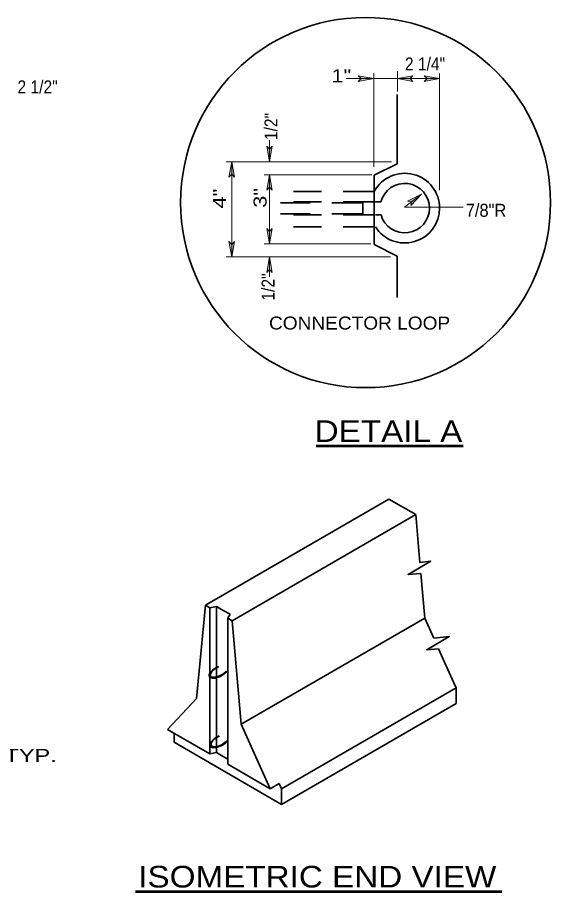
# Model space of a CAD drawing. Extents: x 12.4 to 19.4, y 5.8 to 15.9.
# Drawn here: x 16.975 to 19.442, y 11.795 to 15.837 of the extents above; entities that cross this region are included whole.
import ezdxf
from ezdxf.enums import TextEntityAlignment as Align

# ---------------------------------------------------------------- set-up
doc = ezdxf.new("R2010")
doc.units = 0
doc.header["$LTSCALE"] = 0.024
doc.linetypes.add('LONG_DASHED', pattern=[7.5, 6, -1.5])
for name, color, linetype, lineweight in [('1', 7, 'Continuous', 35), ('10', 7, 'Continuous', 13), ('12', 7, 'Continuous', 53)]:
    doc.layers.add(name, color=color, linetype=linetype, lineweight=lineweight)

msp = doc.modelspace()

# ---------------------------------------------------------------- hatches: boundary and pattern name
at = {"layer": '10'}
for points in [[(18.5521, 15.5671), (18.6236, 15.5545), (18.5521, 15.5419), (18.5656, 15.5545)], [(18.8053, 15.542), (18.7338, 15.5546), (18.8053, 15.5672), (18.7918, 15.5546)], [(18.8573, 15.5672), (18.9288, 15.5546), (18.8573, 15.542), (18.8708, 15.5546)], [(18.1544, 15.2418), (18.1418, 15.1703), (18.1292, 15.2418), (18.1418, 15.2283)], [(17.9538, 15.0988), (17.9664, 15.1703), (17.979, 15.0988), (17.9664, 15.1123)], [(18.1292, 15.0388), (18.1418, 15.1103), (18.1544, 15.0388), (18.1418, 15.0523)], [(18.7808, 14.9881), (18.8456, 15.0208), (18.7959, 14.9679), (18.7992, 14.9861)], [(18.1544, 14.8614), (18.1418, 14.7899), (18.1292, 14.8614), (18.1418, 14.8479)], [(17.979, 14.8014), (17.9664, 14.7299), (17.9538, 14.8014), (17.9664, 14.7879)], [(18.1292, 14.6584), (18.1418, 14.7299), (18.1544, 14.6584), (18.1418, 14.6719)]]:
    msp.add_hatch(color=256, dxfattribs=at).paths.add_polyline_path(points)

# ---------------------------------------------------------------- linework, layer by layer
at = {"layer": '1'}
for p, q in [((18.7329, 15.161), (18.7329, 15.4814)), ((18.6261, 15.1076), (18.7329, 15.161)), ((18.6261, 14.7874), (18.6261, 15.1076)), ((18.6261, 14.9846), (18.657, 14.9846)), ((18.6315, 14.9245), (18.6575, 14.9245)), ((18.6261, 14.7874), (18.7329, 14.7341)), ((18.7329, 14.5422), (18.7329, 14.7341)), ((17.8447, 13.1191), (18.6943, 13.6096)), ((18.8187, 13.5379), (18.6943, 13.6096)), ((17.969, 13.0473), (18.8187, 13.5379)), ((18.8187, 13.5379), (18.8377, 13.3173)), ((18.8601, 13.0593), (18.8422, 13.2662)), ((17.8032, 12.6883), (17.8447, 13.1191)), ((17.8654, 13.1071), (17.8447, 13.1191)), ((17.8964, 13.1131), (17.8654, 13.1071)), ((17.8654, 13.1071), (17.8654, 12.8057)), ((17.9275, 13.0951), (17.8964, 13.1131)), ((17.8964, 13.1131), (17.8964, 12.832)), ((17.9587, 13.0772), (17.9275, 13.0951)), ((17.9587, 13.0772), (17.9483, 13.0593)), ((17.9483, 13.0593), (17.969, 13.0473)), ((17.9483, 13.0593), (17.9483, 12.3832)), ((18.0105, 12.5686), (18.8601, 13.0593)), ((18.8601, 13.0593), (18.9019, 12.9662)), ((17.969, 13.0473), (18.0105, 12.5686)), ((18.9943, 12.7603), (18.9239, 12.9173)), ((17.8964, 12.4371), (17.8964, 12.832)), ((17.8654, 12.4311), (17.8654, 12.7849)), ((17.8997, 12.7822), (17.8998, 12.7822)), ((18.197, 12.2695), (19.0052, 12.7362)), ((18.9943, 12.7603), (19.0052, 12.7362)), ((19.0052, 12.6644), (19.0052, 12.7362)), ((17.8032, 12.6883), (17.669, 12.5444)), ((18.197, 12.1978), (19.0052, 12.6643)), ((17.669, 12.5444), (17.8654, 12.4311)), ((18.0105, 12.5686), (18.1447, 12.2698)), ((17.6995, 12.4849), (17.6995, 12.5261)), ((18.197, 12.1978), (17.6996, 12.485)), ((17.8964, 12.4371), (17.8654, 12.4311)), ((17.9275, 12.4192), (17.8964, 12.4371)), ((17.9483, 12.4072), (17.9275, 12.4192)), ((18.1447, 12.2698), (17.9483, 12.3832)), ((18.1861, 12.2938), (18.1447, 12.2698)), ((18.1861, 12.2938), (18.197, 12.2695)), ((18.197, 12.1978), (18.197, 12.2695))]:
    msp.add_line(p, q, dxfattribs=at)
at = {"layer": '1', "linetype": 'LONG_DASHED'}
for p, q in [((18.6261, 15.0331), (18.2521, 15.0331)), ((18.5732, 14.9802), (18.1919, 14.9802)), ((18.6261, 14.9846), (18.2521, 14.9846)), ((18.5732, 14.9802), (18.5732, 14.9292)), ((18.5732, 14.9292), (18.1919, 14.9292)), ((18.6261, 14.9245), (18.2521, 14.9245)), ((18.6261, 14.8691), (18.2521, 14.8691))]:
    msp.add_line(p, q, dxfattribs=at)
at = {"layer": '1'}
msp.add_circle((18.58605, 14.98141), 0.85609, dxfattribs=at)
for centre, major_axis in [((17.90761, 12.81221), (-0.04433, -0.02381)), ((17.90814, 12.81332), (-0.03989, -0.02143)), ((17.91106, 12.49087), (-0.04433, -0.02381)), ((17.91159, 12.49199), (-0.03989, -0.02143))]:
    msp.add_ellipse(centre, major_axis=major_axis, ratio=0.443253, start_param=4.5260757, end_param=8.573904, dxfattribs=at)
at = {"layer": '10'}
for p, q in [((18.6236, 15.5545), (18.5521, 15.5671)), ((18.6236, 15.1472), (18.6236, 15.5795)), ((18.7332, 15.4956), (18.7332, 15.5897)), ((18.7338, 15.5546), (18.8053, 15.5672)), ((18.9288, 15.5546), (18.8573, 15.5672)), ((18.9288, 15.0381), (18.9288, 15.579)), ((18.4964, 15.5546), (18.9288, 15.5546)), ((18.6236, 15.5545), (18.5521, 15.5419)), ((18.7338, 15.5546), (18.8053, 15.542)), ((18.9288, 15.5546), (18.8573, 15.542)), ((18.1418, 15.1703), (18.1292, 15.2418)), ((18.1418, 15.1703), (18.1418, 15.2706)), ((18.1418, 15.1703), (18.1544, 15.2418)), ((18.7061, 15.1703), (17.9414, 15.1703)), ((17.9664, 15.1703), (17.9538, 15.0988)), ((17.9664, 15.1703), (17.979, 15.0988)), ((17.9664, 15.1703), (17.9664, 14.7299)), ((18.6144, 15.1103), (18.1168, 15.1103)), ((18.1418, 15.1103), (18.1292, 15.0388)), ((18.1418, 15.1103), (18.1544, 15.0388)), ((18.1418, 15.1103), (18.1418, 14.7899)), ((18.8456, 15.0208), (18.7655, 14.9609)), ((18.8456, 15.0208), (18.7808, 14.9881)), ((18.8456, 15.0208), (18.7959, 14.9679)), ((19.0385, 14.9609), (18.7655, 14.9609)), ((18.1418, 14.7899), (18.1292, 14.8614)), ((18.1418, 14.7899), (18.1544, 14.8614)), ((17.9664, 14.7299), (17.9538, 14.8014)), ((17.9664, 14.7299), (17.979, 14.8014)), ((18.61, 14.7899), (18.1168, 14.7899)), ((18.7017, 14.7299), (17.9414, 14.7299)), ((18.1418, 14.7299), (18.1292, 14.6584)), ((18.1418, 14.7299), (18.1418, 14.6373)), ((18.1418, 14.7299), (18.1544, 14.6584))]:
    msp.add_line(p, q, dxfattribs=at)
for points in [[(18.5521, 15.5671), (18.5656, 15.5545), (18.5521, 15.5419)], [(18.8053, 15.542), (18.7918, 15.5546), (18.8053, 15.5672)], [(18.8573, 15.5672), (18.8708, 15.5546), (18.8573, 15.542)], [(18.1544, 15.2418), (18.1418, 15.2283), (18.1292, 15.2418)], [(17.9538, 15.0988), (17.9664, 15.1123), (17.979, 15.0988)], [(18.1292, 15.0388), (18.1418, 15.0523), (18.1544, 15.0388)], [(18.7808, 14.9881), (18.7992, 14.9861), (18.7959, 14.9679)], [(18.1544, 14.8614), (18.1418, 14.8479), (18.1292, 14.8614)], [(17.979, 14.8014), (17.9664, 14.7879), (17.9538, 14.8014)], [(18.1292, 14.6584), (18.1418, 14.6719), (18.1544, 14.6584)]]:
    msp.add_lwpolyline(points, dxfattribs=at)
for points in [[(18.5521, 15.5671), (18.6236, 15.5545), (18.5521, 15.5419), (18.5656, 15.5545)], [(18.8053, 15.542), (18.7338, 15.5546), (18.8053, 15.5672), (18.7918, 15.5546)], [(18.8573, 15.5672), (18.9288, 15.5546), (18.8573, 15.542), (18.8708, 15.5546)], [(18.1544, 15.2418), (18.1418, 15.1703), (18.1292, 15.2418), (18.1418, 15.2283)], [(17.9538, 15.0988), (17.9664, 15.1703), (17.979, 15.0988), (17.9664, 15.1123)], [(18.1292, 15.0388), (18.1418, 15.1103), (18.1544, 15.0388), (18.1418, 15.0523)], [(18.7808, 14.9881), (18.8456, 15.0208), (18.7959, 14.9679), (18.7992, 14.9861)], [(18.1544, 14.8614), (18.1418, 14.7899), (18.1292, 14.8614), (18.1418, 14.8479)], [(17.979, 14.8014), (17.9664, 14.7299), (17.9538, 14.8014), (17.9664, 14.7879)], [(18.1292, 14.6584), (18.1418, 14.7299), (18.1544, 14.6584), (18.1418, 14.6719)]]:
    msp.add_lwpolyline(points, close=True, dxfattribs=at)
at = {"layer": '10', "lineweight": 35}
for points in [[(18.8377, 13.3173), (18.8876, 13.3229), (18.7831, 13.2614), (18.8422, 13.2662)], [(18.9019, 12.9662), (18.9736, 12.9743), (18.869, 12.9128), (18.924, 12.9173)]]:
    msp.add_lwpolyline(points, dxfattribs=at)
for radius, start, end in [(0.16127, 0, 151.30134), (0.11435, 0, 165.30722), (0.16127, 212.44984, 0), (0.11435, 195.7776, 0)]:
    msp.add_arc((18.76756, 14.95563), radius, start, end, dxfattribs=at)
at = {"layer": '12'}
for p, q in [((18.3569, 13.8557), (19.0383, 13.8557)), ((17.5211, 11.7948), (19.2162, 11.7948))]:
    msp.add_line(p, q, dxfattribs=at)

# ---------------------------------------------------------------- texts
for s, width, p in [('2 1/4"', 0.9, (18.7681, 15.5926)), ('1"', 1.25, (18.4282, 15.5379)), ('2 1/2"', 0.9, (16.9749, 15.4865)), ('7/8"R', 0.95, (19.0496, 14.9156)), ('CONNECTOR LOOP', 1.1, (18.1391, 14.3942)), ('2" TYP.', 1.35, (16.7868, 12.3942))]:
    msp.add_text(s, height=0.06, dxfattribs=dict(at, width=width)).set_placement(p)
for s, width, p in [('1/2"', 0.9, (18.1783, 15.2702)), ('4"', 1.25, (17.9397, 14.954)), ('3"', 1.25, (18.1276, 14.9572)), ('1/2"', 0.9, (18.1648, 14.5279))]:
    msp.add_text(s, height=0.06, rotation=90, dxfattribs=dict(at, width=width)).set_placement(p)
at = {"layer": '12', "width": 1.15}
for s, p in [('DETAIL A', (18.6921, 13.8743)), ('ISOMETRIC END VIEW', (18.3628, 11.8134))]:
    msp.add_text(s, height=0.1, dxfattribs=at).set_placement(p, align=Align.CENTER)

doc.saveas('drawing.dxf')
